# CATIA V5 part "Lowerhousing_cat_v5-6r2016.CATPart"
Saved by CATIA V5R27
Part number: Lowerhousing
Bounding box of the stored display mesh (mm): x -75 to 75, y -40 to 40, z -68 to -0.1
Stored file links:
  E:\_Deepak\2017_Deepak\CATIA\Resources\Tutorial Files\Tutorials\c12_catia_v5_6r2015_tut\c12Tut1\Lowerhousing_cat_v5-6r2016.CATPart
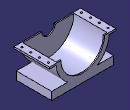
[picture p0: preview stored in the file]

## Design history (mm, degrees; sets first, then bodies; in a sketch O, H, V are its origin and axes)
Body1 (main body)
  Sketch1 on zx-plane, origin (0, 0, 0), H (-1, 0, 0), V (0, 0, 1)
    line L1 (-75, -0.1) -> (75, -0.1)
    point P1 (-75, -0.1)
    arc A1 centre (0, 0) radius 60 from (-59.8598, -4.1) to (-33.1662, -50) ccw
    line L2 (-75, -4.1) -> (-59.8598, -4.1)
    line L3 (-70, -68) -> (70, -68)
    point P6 (70, -68)
    line L4 (-70, -50) -> (-33.1662, -50)
    line L5 (70, -68) -> (70, -50)
    line L6 (-70, -68) -> (-70, -50)
    arc A2 centre (0, 0) radius 60 from (33.1662, -50) to (59.8598, -4.1) ccw
    point P10 (33.1662, -50)
    line L7 (33.1662, -50) -> (70, -50)
    line L8 (75, -4.1) -> (75, -0.1)
    line L9 (-75, -4.1) -> (-75, -0.1)
    point P11 (59.8598, -4.1)
    line L10 (59.8598, -4.1) -> (75, -4.1)
    length L1 = 150
    distance P1 V = 75
    distance L2 L1 = 4
    distance L3 H = 68
    distance L4 L3 = 18
    distance P6 V = 70
    length L3 = 140
    radius A1 = 60
    horizontal: L1 H, L2 H, L3 H, L4 H, L7 H, L10 H
    vertical: L6 V, L5 V, L8 V, L9 V
    coincidence: L4 P10, A1 A2, L4 L7, L2 P11, L2 L10
  Pad1: profile Sketch1, direction (0, 1, 0), length 40, mirrored extent
  Sketch2 on face of Pad1, origin (0, 0, -0.1), H (1, 0, 0), V (0, 1, 0)
    circle A1 centre (-67.5, 30) radius 2
    point P1 (-67.5, 30)
    reference projected line E1 (-75, 40) -> (75, 40) from edge of Pad1
    reference projected line E2 (-75, -40) -> (-75, 40) from edge of Pad1
    radius A1 = 2
    distance E1 P1 = 10
    distance E2 P1 = 7.5
  Pocket1: profile Sketch2, direction (0, 0, -1), through (limit type 6)
  RectPattern1: of Pocket1, direction 1 instances 4, spacing 20, along edge of Pad1 reversed, direction 2 instances 2, spacing 135, along edge of Pad1 reversed
  Sketch3 on face of Pad1, origin (0, 0, -0.1), H (1, 0, 0), V (0, 1, 0)
    point P1 (0, -37.5)
    line L1 (0, -37.5) -> (57.5, -37.5)
    line L2 (57.5, -37.5) -> (57.5, 37.5)
    line L3 (57.5, 37.5) -> (0, 37.5)
    line L4 (0, 37.5) -> (0, -37.5)
    reference projected line E1 (-75, 40) -> (75, 40) from edge [face of Pad1 from Sketch1.L1 | end face of Pad1]
    reference projected line E2 (-75, -40) -> (75, -40) from edge [start face of Pad1 | face of Pad1 from Sketch1.L1]
    length L3 = 57.5
    distance L3 E1 = 2.5
    distance L1 E2 = 2.5
    coincidence: P1 V
    horizontal: L1 H, L3 H
    vertical: L2 V, L4 V
  Groove1: profile Sketch3, axis edge of Sketch3, angle 360
  Sketch4 on face of Pad1, origin (0, 40, 0), H (-1, 0, 0), V (0, 0, 1)
    circle A1 centre (0, 0) radius 15
    circle A2 centre (0, 0) radius 49
    radius A2 = 49
    radius A1 = 15
  MultiPocket1: profile Sketch4, domains (length 25.4; length 279.4)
